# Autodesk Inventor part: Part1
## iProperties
Shininess: 64.0
Length Units: 11269
Angle Units: 11279
Time Units: 11290
Mass Units: 11283
Length Display Precision: 3
Angle Display Precision: 2
Compacted: True
Part Number: Part1
Document SubType Name: Modeling
Created: 2004-08
Designer: John Blackburn
Manufacturer: Standard
Standards Organization: Custom
Density: 0.0
Volumn: 0.0
Area: 0.0
PropertySet Name: Model Information
Control State: 0
Master: False
Checked Out: False
Author: John Blackburn
